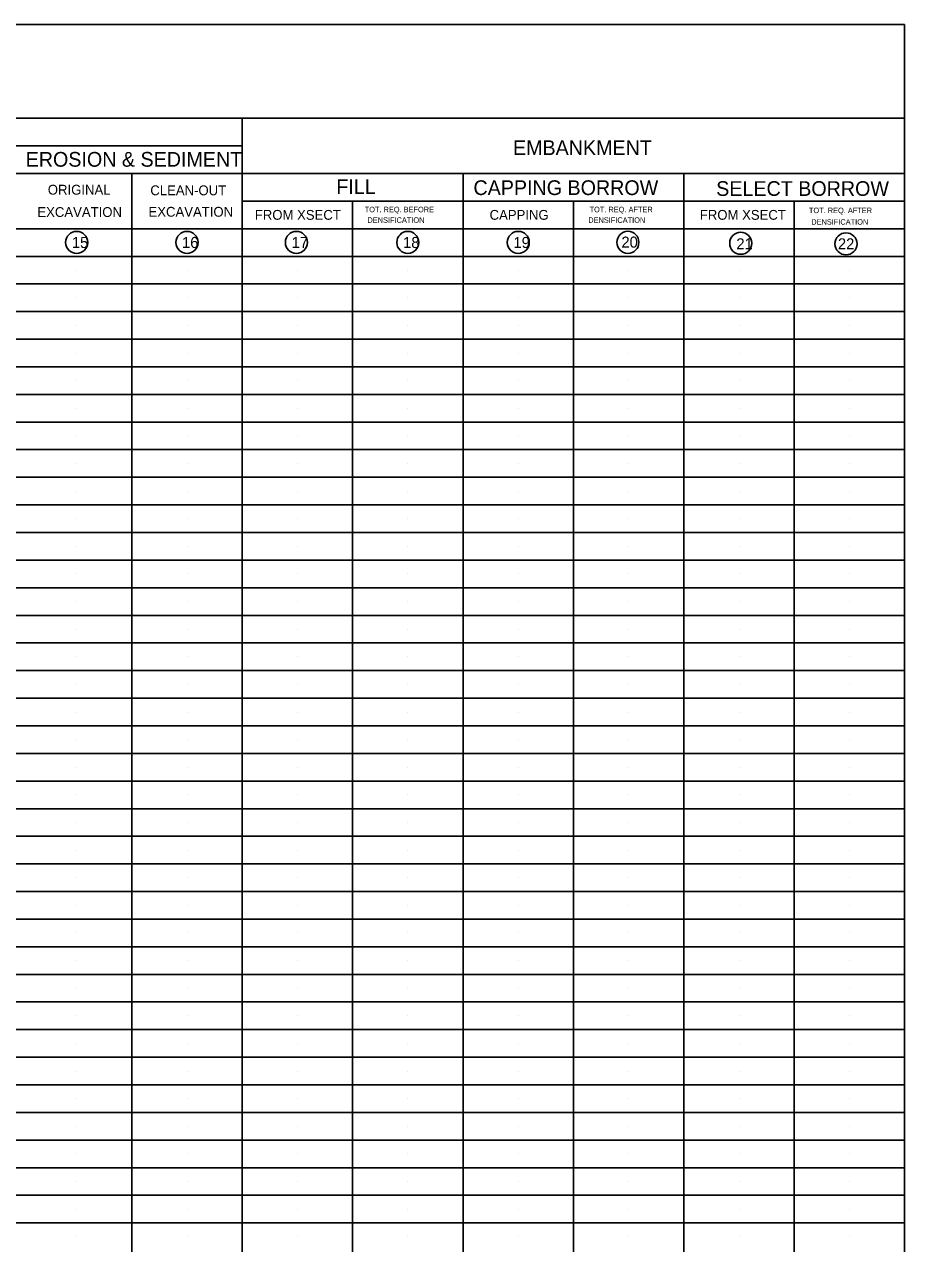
# Model space of a CAD drawing. Extents: x 1.3 to 38.6, y 0 to 21.1.
# Drawn here: x 15.32 to 22.5, y 11.12 to 21.05 of the extents above; entities that cross this region are included whole.
import ezdxf

# ---------------------------------------------------------------- set-up
doc = ezdxf.new("R2010")
doc.units = 0
for name, color, linetype in [('G-ANNO-TABL', 7, 'Continuous'), ('G-ANNO-TITL', 7, 'Continuous'), ('G-USER-LINE', 7, 'Continuous')]:
    doc.layers.add(name, color=color, linetype=linetype)

msp = doc.modelspace()

# ---------------------------------------------------------------- linework, layer by layer
at = {"layer": 'G-ANNO-TABL'}
for p, q in [((2.248, 21.055), (22.498, 21.055)), ((22.498, 21.055), (22.498, 1.165)), ((2.248, 20.29), (22.498, 20.29)), ((17.098, 20.2901), (17.098, 4.54)), ((2.698, 20.065), (17.098, 20.065)), ((2.698, 19.84), (22.498, 19.84)), ((16.198, 19.8401), (16.198, 4.54)), ((18.898, 19.84), (18.898, 4.54)), ((20.698, 19.84), (20.698, 4.54)), ((17.098, 19.615), (22.498, 19.615)), ((17.998, 19.6151), (17.998, 4.54)), ((19.798, 19.6151), (19.798, 4.54)), ((21.598, 19.615), (21.598, 1.165)), ((2.698, 19.39), (22.498, 19.39)), ((2.248, 19.165), (22.498, 19.165)), ((2.698, 18.94), (22.498, 18.94)), ((2.698, 18.715), (22.498, 18.715)), ((2.698, 18.49), (22.498, 18.49)), ((2.698, 18.265), (22.498, 18.265)), ((2.698, 18.04), (22.498, 18.04)), ((2.698, 17.815), (22.498, 17.815)), ((2.698, 17.59), (22.498, 17.59)), ((2.698, 17.365), (22.498, 17.365)), ((2.698, 17.14), (22.498, 17.14)), ((2.698, 16.915), (22.498, 16.915)), ((2.698, 16.69), (22.498, 16.69)), ((2.698, 16.465), (22.498, 16.465)), ((2.698, 16.24), (22.498, 16.24)), ((2.698, 16.015), (22.498, 16.015)), ((2.698, 15.79), (22.498, 15.79)), ((2.698, 15.565), (22.498, 15.565)), ((2.698, 15.34), (22.498, 15.34)), ((2.698, 15.115), (22.498, 15.115)), ((2.698, 14.89), (22.498, 14.89)), ((2.698, 14.665), (22.498, 14.665)), ((2.698, 14.44), (22.498, 14.44)), ((2.698, 14.215), (22.498, 14.215)), ((2.698, 13.99), (22.498, 13.99)), ((2.698, 13.765), (22.498, 13.765)), ((2.698, 13.54), (22.498, 13.54)), ((2.698, 13.315), (22.498, 13.315)), ((2.698, 13.09), (22.498, 13.09)), ((2.698, 12.865), (22.498, 12.865)), ((2.698, 12.64), (22.498, 12.64)), ((2.698, 12.415), (22.498, 12.415)), ((2.698, 12.19), (22.498, 12.19)), ((2.698, 11.965), (22.498, 11.965)), ((2.698, 11.74), (22.498, 11.74)), ((2.698, 11.515), (22.498, 11.515)), ((2.698, 11.29), (22.498, 11.29))]:
    msp.add_line(p, q, dxfattribs=at)
at = {"layer": 'G-ANNO-TITL'}
for centre in [(15.7479, 19.278), (16.6479, 19.278), (17.5398, 19.278), (18.4479, 19.278), (19.3479, 19.278), (20.2416, 19.2789), (21.1619, 19.272), (22.02, 19.267)]:
    msp.add_circle(centre, 0.09, dxfattribs=at)
at = {"layer": 'G-USER-LINE'}
for p, q in [((17.548, 19.5025), (17.548, 19.5025)), ((18.448, 19.5025), (18.448, 19.5025)), ((19.348, 19.5025), (19.348, 19.5025)), ((20.248, 19.5025), (20.248, 19.5025)), ((21.148, 19.5025), (21.148, 19.5025)), ((22.048, 19.5025), (22.048, 19.5025)), ((15.748, 19.2775), (15.748, 19.2775)), ((16.648, 19.2775), (16.648, 19.2775)), ((17.548, 19.2775), (17.548, 19.2775)), ((18.448, 19.2775), (18.448, 19.2775)), ((19.348, 19.2775), (19.348, 19.2775)), ((20.248, 19.2775), (20.248, 19.2775)), ((21.148, 19.2775), (21.148, 19.2775)), ((22.048, 19.2775), (22.048, 19.2775)), ((15.748, 19.0525), (15.748, 19.0525)), ((16.648, 19.0525), (16.648, 19.0525)), ((17.548, 19.0525), (17.548, 19.0525)), ((18.448, 19.0525), (18.448, 19.0525)), ((19.348, 19.0525), (19.348, 19.0525)), ((20.248, 19.0525), (20.248, 19.0525)), ((21.148, 19.0525), (21.148, 19.0525)), ((22.048, 19.0525), (22.048, 19.0525)), ((15.748, 18.8275), (15.748, 18.8275)), ((16.648, 18.8275), (16.648, 18.8275)), ((17.548, 18.8275), (17.548, 18.8275)), ((18.448, 18.8275), (18.448, 18.8275)), ((19.348, 18.8275), (19.348, 18.8275)), ((20.248, 18.8275), (20.248, 18.8275)), ((21.148, 18.8275), (21.148, 18.8275)), ((22.048, 18.8275), (22.048, 18.8275)), ((15.748, 18.6025), (15.748, 18.6025)), ((16.648, 18.6025), (16.648, 18.6025)), ((17.548, 18.6025), (17.548, 18.6025)), ((18.448, 18.6025), (18.448, 18.6025)), ((19.348, 18.6025), (19.348, 18.6025)), ((20.248, 18.6025), (20.248, 18.6025)), ((21.148, 18.6025), (21.148, 18.6025)), ((22.048, 18.6025), (22.048, 18.6025)), ((15.748, 18.3775), (15.748, 18.3775)), ((16.648, 18.3775), (16.648, 18.3775)), ((17.548, 18.3775), (17.548, 18.3775)), ((18.448, 18.3775), (18.448, 18.3775)), ((19.348, 18.3775), (19.348, 18.3775)), ((20.248, 18.3775), (20.248, 18.3775)), ((21.148, 18.3775), (21.148, 18.3775)), ((22.048, 18.3775), (22.048, 18.3775)), ((15.748, 18.1525), (15.748, 18.1525)), ((16.648, 18.1525), (16.648, 18.1525)), ((17.548, 18.1525), (17.548, 18.1525)), ((18.448, 18.1525), (18.448, 18.1525)), ((19.348, 18.1525), (19.348, 18.1525)), ((20.248, 18.1525), (20.248, 18.1525)), ((21.148, 18.1525), (21.148, 18.1525)), ((22.048, 18.1525), (22.048, 18.1525)), ((15.748, 17.9275), (15.748, 17.9275)), ((16.648, 17.9275), (16.648, 17.9275)), ((17.548, 17.9275), (17.548, 17.9275)), ((18.448, 17.9275), (18.448, 17.9275)), ((19.348, 17.9275), (19.348, 17.9275)), ((20.248, 17.9275), (20.248, 17.9275)), ((21.148, 17.9275), (21.148, 17.9275)), ((22.048, 17.9275), (22.048, 17.9275)), ((15.748, 17.7025), (15.748, 17.7025)), ((16.648, 17.7025), (16.648, 17.7025)), ((17.548, 17.7025), (17.548, 17.7025)), ((18.448, 17.7025), (18.448, 17.7025)), ((19.348, 17.7025), (19.348, 17.7025)), ((20.248, 17.7025), (20.248, 17.7025)), ((21.148, 17.7025), (21.148, 17.7025)), ((22.048, 17.7025), (22.048, 17.7025)), ((15.748, 17.4775), (15.748, 17.4775)), ((16.648, 17.4775), (16.648, 17.4775)), ((17.548, 17.4775), (17.548, 17.4775)), ((18.448, 17.4775), (18.448, 17.4775)), ((19.348, 17.4775), (19.348, 17.4775)), ((20.248, 17.4775), (20.248, 17.4775)), ((21.148, 17.4775), (21.148, 17.4775)), ((22.048, 17.4775), (22.048, 17.4775)), ((15.748, 17.2525), (15.748, 17.2525)), ((16.648, 17.2525), (16.648, 17.2525)), ((17.548, 17.2525), (17.548, 17.2525)), ((18.448, 17.2525), (18.448, 17.2525)), ((19.348, 17.2525), (19.348, 17.2525)), ((20.248, 17.2525), (20.248, 17.2525)), ((21.148, 17.2525), (21.148, 17.2525)), ((22.048, 17.2525), (22.048, 17.2525)), ((15.748, 17.0275), (15.748, 17.0275)), ((16.648, 17.0275), (16.648, 17.0275)), ((17.548, 17.0275), (17.548, 17.0275)), ((18.448, 17.0275), (18.448, 17.0275)), ((19.348, 17.0275), (19.348, 17.0275)), ((20.248, 17.0275), (20.248, 17.0275)), ((21.148, 17.0275), (21.148, 17.0275)), ((22.048, 17.0275), (22.048, 17.0275)), ((15.748, 16.8025), (15.748, 16.8025)), ((16.648, 16.8025), (16.648, 16.8025)), ((17.548, 16.8025), (17.548, 16.8025)), ((18.448, 16.8025), (18.448, 16.8025)), ((19.348, 16.8025), (19.348, 16.8025)), ((20.248, 16.8025), (20.248, 16.8025)), ((21.148, 16.8025), (21.148, 16.8025)), ((22.048, 16.8025), (22.048, 16.8025)), ((15.748, 16.5775), (15.748, 16.5775)), ((16.648, 16.5775), (16.648, 16.5775)), ((17.548, 16.5775), (17.548, 16.5775)), ((18.448, 16.5775), (18.448, 16.5775)), ((19.348, 16.5775), (19.348, 16.5775)), ((20.248, 16.5775), (20.248, 16.5775)), ((21.148, 16.5775), (21.148, 16.5775)), ((22.048, 16.5775), (22.048, 16.5775)), ((15.748, 16.3525), (15.748, 16.3525)), ((16.648, 16.3525), (16.648, 16.3525)), ((17.548, 16.3525), (17.548, 16.3525)), ((18.448, 16.3525), (18.448, 16.3525)), ((19.348, 16.3525), (19.348, 16.3525)), ((20.248, 16.3525), (20.248, 16.3525)), ((21.148, 16.3525), (21.148, 16.3525)), ((22.048, 16.3525), (22.048, 16.3525)), ((15.748, 16.1275), (15.748, 16.1275)), ((16.648, 16.1275), (16.648, 16.1275)), ((17.548, 16.1275), (17.548, 16.1275)), ((18.448, 16.1275), (18.448, 16.1275)), ((19.348, 16.1275), (19.348, 16.1275)), ((20.248, 16.1275), (20.248, 16.1275)), ((21.148, 16.1275), (21.148, 16.1275)), ((22.048, 16.1275), (22.048, 16.1275)), ((15.748, 15.9025), (15.748, 15.9025)), ((16.648, 15.9025), (16.648, 15.9025)), ((17.548, 15.9025), (17.548, 15.9025)), ((18.448, 15.9025), (18.448, 15.9025)), ((19.348, 15.9025), (19.348, 15.9025)), ((20.248, 15.9025), (20.248, 15.9025)), ((21.148, 15.9025), (21.148, 15.9025)), ((22.048, 15.9025), (22.048, 15.9025)), ((15.748, 15.6775), (15.748, 15.6775)), ((16.648, 15.6775), (16.648, 15.6775)), ((17.548, 15.6775), (17.548, 15.6775)), ((18.448, 15.6775), (18.448, 15.6775)), ((19.348, 15.6775), (19.348, 15.6775)), ((20.248, 15.6775), (20.248, 15.6775)), ((21.148, 15.6775), (21.148, 15.6775)), ((22.048, 15.6775), (22.048, 15.6775)), ((15.748, 15.4525), (15.748, 15.4525)), ((16.648, 15.4525), (16.648, 15.4525)), ((17.548, 15.4525), (17.548, 15.4525)), ((18.448, 15.4525), (18.448, 15.4525)), ((19.348, 15.4525), (19.348, 15.4525)), ((20.248, 15.4525), (20.248, 15.4525)), ((21.148, 15.4525), (21.148, 15.4525)), ((22.048, 15.4525), (22.048, 15.4525)), ((15.748, 15.2275), (15.748, 15.2275)), ((16.648, 15.2275), (16.648, 15.2275)), ((17.548, 15.2275), (17.548, 15.2275)), ((18.448, 15.2275), (18.448, 15.2275)), ((19.348, 15.2275), (19.348, 15.2275)), ((20.248, 15.2275), (20.248, 15.2275)), ((21.148, 15.2275), (21.148, 15.2275)), ((22.048, 15.2275), (22.048, 15.2275)), ((15.748, 15.0025), (15.748, 15.0025)), ((16.648, 15.0025), (16.648, 15.0025)), ((17.548, 15.0025), (17.548, 15.0025)), ((18.448, 15.0025), (18.448, 15.0025)), ((19.348, 15.0025), (19.348, 15.0025)), ((20.248, 15.0025), (20.248, 15.0025)), ((21.148, 15.0025), (21.148, 15.0025)), ((22.048, 15.0025), (22.048, 15.0025)), ((15.748, 14.7775), (15.748, 14.7775)), ((16.648, 14.7775), (16.648, 14.7775)), ((17.548, 14.7775), (17.548, 14.7775)), ((18.448, 14.7775), (18.448, 14.7775)), ((19.348, 14.7775), (19.348, 14.7775)), ((20.248, 14.7775), (20.248, 14.7775)), ((21.148, 14.7775), (21.148, 14.7775)), ((22.048, 14.7775), (22.048, 14.7775)), ((15.748, 14.5525), (15.748, 14.5525)), ((16.648, 14.5525), (16.648, 14.5525)), ((17.548, 14.5525), (17.548, 14.5525)), ((18.448, 14.5525), (18.448, 14.5525)), ((19.348, 14.5525), (19.348, 14.5525)), ((20.248, 14.5525), (20.248, 14.5525)), ((21.148, 14.5525), (21.148, 14.5525)), ((22.048, 14.5525), (22.048, 14.5525)), ((15.748, 14.3275), (15.748, 14.3275)), ((16.648, 14.3275), (16.648, 14.3275)), ((17.548, 14.3275), (17.548, 14.3275)), ((18.448, 14.3275), (18.448, 14.3275)), ((19.348, 14.3275), (19.348, 14.3275)), ((20.248, 14.3275), (20.248, 14.3275)), ((21.148, 14.3275), (21.148, 14.3275)), ((22.048, 14.3275), (22.048, 14.3275)), ((15.748, 14.1025), (15.748, 14.1025)), ((16.648, 14.1025), (16.648, 14.1025)), ((17.548, 14.1025), (17.548, 14.1025)), ((18.448, 14.1025), (18.448, 14.1025)), ((19.348, 14.1025), (19.348, 14.1025)), ((20.248, 14.1025), (20.248, 14.1025)), ((21.148, 14.1025), (21.148, 14.1025)), ((22.048, 14.1025), (22.048, 14.1025)), ((15.748, 13.8775), (15.748, 13.8775)), ((16.648, 13.8775), (16.648, 13.8775)), ((17.548, 13.8775), (17.548, 13.8775)), ((18.448, 13.8775), (18.448, 13.8775)), ((19.348, 13.8775), (19.348, 13.8775)), ((20.248, 13.8775), (20.248, 13.8775)), ((21.148, 13.8775), (21.148, 13.8775)), ((22.048, 13.8775), (22.048, 13.8775)), ((15.748, 13.6525), (15.748, 13.6525)), ((16.648, 13.6525), (16.648, 13.6525)), ((17.548, 13.6525), (17.548, 13.6525)), ((18.448, 13.6525), (18.448, 13.6525)), ((19.348, 13.6525), (19.348, 13.6525)), ((20.248, 13.6525), (20.248, 13.6525)), ((21.148, 13.6525), (21.148, 13.6525)), ((22.048, 13.6525), (22.048, 13.6525)), ((15.748, 13.4275), (15.748, 13.4275)), ((16.648, 13.4275), (16.648, 13.4275)), ((17.548, 13.4275), (17.548, 13.4275)), ((18.448, 13.4275), (18.448, 13.4275)), ((19.348, 13.4275), (19.348, 13.4275)), ((20.248, 13.4275), (20.248, 13.4275)), ((21.148, 13.4275), (21.148, 13.4275)), ((22.048, 13.4275), (22.048, 13.4275)), ((15.748, 13.2025), (15.748, 13.2025)), ((16.648, 13.2025), (16.648, 13.2025)), ((17.548, 13.2025), (17.548, 13.2025)), ((18.448, 13.2025), (18.448, 13.2025)), ((19.348, 13.2025), (19.348, 13.2025)), ((20.248, 13.2025), (20.248, 13.2025)), ((21.148, 13.2025), (21.148, 13.2025)), ((22.048, 13.2025), (22.048, 13.2025)), ((15.748, 12.9775), (15.748, 12.9775)), ((16.648, 12.9775), (16.648, 12.9775)), ((17.548, 12.9775), (17.548, 12.9775)), ((18.448, 12.9775), (18.448, 12.9775)), ((19.348, 12.9775), (19.348, 12.9775)), ((20.248, 12.9775), (20.248, 12.9775)), ((21.148, 12.9775), (21.148, 12.9775)), ((22.048, 12.9775), (22.048, 12.9775)), ((15.748, 12.7525), (15.748, 12.7525)), ((16.648, 12.7525), (16.648, 12.7525)), ((17.548, 12.7525), (17.548, 12.7525)), ((18.448, 12.7525), (18.448, 12.7525)), ((19.348, 12.7525), (19.348, 12.7525)), ((20.248, 12.7525), (20.248, 12.7525)), ((21.148, 12.7525), (21.148, 12.7525)), ((22.048, 12.7525), (22.048, 12.7525)), ((15.748, 12.5275), (15.748, 12.5275)), ((16.648, 12.5275), (16.648, 12.5275)), ((17.548, 12.5275), (17.548, 12.5275)), ((18.448, 12.5275), (18.448, 12.5275)), ((19.348, 12.5275), (19.348, 12.5275)), ((20.248, 12.5275), (20.248, 12.5275)), ((21.148, 12.5275), (21.148, 12.5275)), ((22.048, 12.5275), (22.048, 12.5275)), ((15.748, 12.3025), (15.748, 12.3025)), ((16.648, 12.3025), (16.648, 12.3025)), ((17.548, 12.3025), (17.548, 12.3025)), ((18.448, 12.3025), (18.448, 12.3025)), ((19.348, 12.3025), (19.348, 12.3025)), ((20.248, 12.3025), (20.248, 12.3025)), ((21.148, 12.3025), (21.148, 12.3025)), ((22.048, 12.3025), (22.048, 12.3025)), ((15.748, 12.0775), (15.748, 12.0775)), ((16.648, 12.0775), (16.648, 12.0775)), ((17.548, 12.0775), (17.548, 12.0775)), ((18.448, 12.0775), (18.448, 12.0775)), ((19.348, 12.0775), (19.348, 12.0775)), ((20.248, 12.0775), (20.248, 12.0775)), ((21.148, 12.0775), (21.148, 12.0775)), ((22.048, 12.0775), (22.048, 12.0775)), ((15.748, 11.8525), (15.748, 11.8525)), ((16.648, 11.8525), (16.648, 11.8525)), ((17.548, 11.8525), (17.548, 11.8525)), ((18.448, 11.8525), (18.448, 11.8525)), ((19.348, 11.8525), (19.348, 11.8525)), ((20.248, 11.8525), (20.248, 11.8525)), ((21.148, 11.8525), (21.148, 11.8525)), ((22.048, 11.8525), (22.048, 11.8525)), ((15.748, 11.6275), (15.748, 11.6275)), ((16.648, 11.6275), (16.648, 11.6275)), ((17.548, 11.6275), (17.548, 11.6275)), ((18.448, 11.6275), (18.448, 11.6275)), ((19.348, 11.6275), (19.348, 11.6275)), ((20.248, 11.6275), (20.248, 11.6275)), ((21.148, 11.6275), (21.148, 11.6275)), ((22.048, 11.6275), (22.048, 11.6275)), ((15.748, 11.4025), (15.748, 11.4025)), ((16.648, 11.4025), (16.648, 11.4025)), ((17.548, 11.4025), (17.548, 11.4025)), ((18.448, 11.4025), (18.448, 11.4025)), ((19.348, 11.4025), (19.348, 11.4025)), ((20.248, 11.4025), (20.248, 11.4025)), ((21.148, 11.4025), (21.148, 11.4025)), ((22.048, 11.4025), (22.048, 11.4025)), ((15.748, 11.1775), (15.748, 11.1775)), ((16.648, 11.1775), (16.648, 11.1775)), ((17.548, 11.1775), (17.548, 11.1775)), ((18.448, 11.1775), (18.448, 11.1775)), ((19.348, 11.1775), (19.348, 11.1775)), ((20.248, 11.1775), (20.248, 11.1775)), ((21.148, 11.1775), (21.148, 11.1775)), ((22.048, 11.1775), (22.048, 11.1775))]:
    msp.add_line(p, q, dxfattribs=at)

# ---------------------------------------------------------------- texts
at = {"layer": 'G-ANNO-TITL'}
for s, height, p in [('EMBANKMENT', 0.12, (19.3051, 19.9905)), ('EROSION & SEDIMENT', 0.12, (15.3324, 19.8955)), ('FILL', 0.12, (17.8648, 19.6725)), ('CAPPING BORROW', 0.12, (18.9828, 19.6645)), ('SELECT BORROW', 0.12, (20.9618, 19.6575)), ('ORIGINAL', 0.08, (15.5131, 19.668)), ('CLEAN-OUT', 0.08, (16.3487, 19.663)), ('TOT. REQ. BEFORE', 0.044994, (18.0964, 19.524)), ('TOT. REQ. AFTER', 0.045, (19.9297, 19.524)), ('EXCAVATION', 0.08, (15.4279, 19.486)), ('EXCAVATION', 0.08, (16.3339, 19.488)), ('FROM XSECT', 0.08, (17.2003, 19.463)), ('DENSIFICATION', 0.044994, (18.1189, 19.438)), ('CAPPING', 0.08, (19.1146, 19.463)), ('DENSIFICATION', 0.044994, (19.9189, 19.438)), ('FROM XSECT', 0.08, (20.8283, 19.463)), ('TOT. REQ. AFTER', 0.045, (21.7177, 19.517)), ('DENSIFICATION', 0.044994, (21.7369, 19.423)), ('15', 0.09, (15.709, 19.233)), ('16', 0.09, (16.607, 19.233)), ('17', 0.09, (17.501, 19.233)), ('18', 0.09, (18.409, 19.233)), ('19', 0.09, (19.309, 19.233)), ('20', 0.09, (20.189, 19.236)), ('21', 0.09, (21.126, 19.222)), ('22', 0.09, (21.954, 19.222))]:
    msp.add_text(s, height=height, dxfattribs=at).set_placement(p)

doc.saveas('drawing.dxf')
